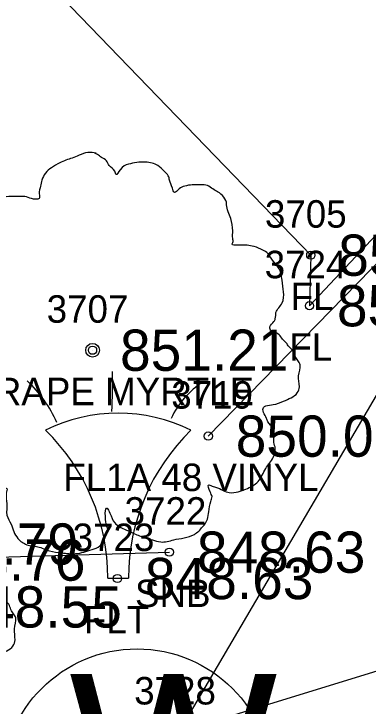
# Model space of a CAD drawing. Extents: x 1622501 to 1626664, y 1117816 to 1121579.
# Drawn here: x 1624875.03 to 1624887.93, y 1120136.59 to 1120161.78 of the extents above; entities that cross this region are included whole.
import ezdxf

# ---------------------------------------------------------------- set-up
doc = ezdxf.new("R2010")
doc.units = 0
for name, color, linetype in [('RD_EX_BldgApp', 7, 'Continuous'), ('RD_EX_BldgApp_txCode', 7, 'Continuous'), ('RD_EX_Fence_Other', 7, 'Continuous'), ('RD_EX_Fence_Other_txCode', 7, 'Continuous'), ('RD_EX_TX_BldgApp_ELEV', 7, 'Continuous'), ('RD_EX_TX_Fence_Other_ELEV', 7, 'Continuous'), ('RD_EX_TX_VEG_ELEV', 7, 'Continuous'), ('RD_EX_UT', 7, 'Continuous'), ('RD_EX_VEG', 7, 'Continuous'), ('RD_EX_VEG_txCode', 7, 'Continuous'), ('RD_SMD_Locator', 7, 'Continuous')]:
    doc.layers.add(name, color=color, linetype=linetype)

msp = doc.modelspace()

# ---------------------------------------------------------------- linework, layer by layer
at = {"layer": 'RD_EX_BldgApp'}
for p, q in [((1624870.501, 1120141.902), (1624880.693, 1120142.191)), ((1624878.454, 1120141.249), (1624879.204, 1120141.249))]:
    msp.add_line(p, q, dxfattribs=at)
for centre, radius, start, end in [((1624840.747, 1120148.587), 37.876, 358.0671, 0.2715), ((1624872.136, 1120144.891), 4.895, 24.3279, 46.2665), ((1624883.717, 1120145.642), 3.283, 123.2906, 154.4886), ((1624878.829, 1120141.249), 5.997, 63.7794, 116.2206), ((1624870.954, 1120141.249), 7.5, 0, 45.8366), ((1624886.704, 1120141.249), 7.5, 134.1634, 180)]:
    msp.add_arc(centre, radius, start, end, dxfattribs=at)
at = {"layer": 'RD_EX_Fence_Other'}
for points in [[(1624882.108, 1120146.413), (1624922.827, 1120188.172), (1624952.576, 1120216.9), (1624993.862, 1120256.562), (1625030.931, 1120289.642), (1625069.578, 1120325.996), (1625106.791, 1120358.455), (1625145.388, 1120394.48), (1625163.872, 1120411.002), (1625180.046, 1120426.703), (1625211.372, 1120456.62), (1625250.442, 1120494.547), (1625284.568, 1120527.631), (1625318.686, 1120557.977), (1625317.764, 1120559.821), (1625354.436, 1120595.487), (1625389.434, 1120629.691)], [(1624858.614, 1120181.158), (1624885.841, 1120152.998), (1624885.793, 1120151.157), (1624925.786, 1120193.73), (1624921.287, 1120199.2), (1624921.287, 1120199.2), (1624965.414, 1120242.441), (1624960.474, 1120248.561)]]:
    msp.add_lwpolyline(points, dxfattribs=at)
at = {"layer": 'RD_EX_UT'}
msp.add_circle((1624879.514, 1120133.762), 4.908, dxfattribs=at)
at = {"layer": 'RD_EX_VEG'}
msp.add_lwpolyline([(1624889.699, 1120150.412), (1624881.041, 1120135.648), (1624900.095, 1120141.509), (1624901.078, 1120146.7)], dxfattribs=at)
for centre, radius in [((1624877.895, 1120149.539), 0.25), ((1624877.883, 1120149.52), 0.0001)]:
    msp.add_circle(centre, radius, dxfattribs=at)
for points in [[(1624878.027, 1120156.706), (1624877.727, 1120156.731), (1624877.403, 1120156.631), (1624877.153, 1120156.531), (1624876.928, 1120156.456), (1624876.703, 1120156.356), (1624876.403, 1120156.181), (1624876.178, 1120155.981), (1624876.053, 1120155.731), (1624876.003, 1120155.507), (1624875.953, 1120155.232), (1624875.953, 1120155.057), (1624875.828, 1120155.032), (1624875.678, 1120155.057), (1624875.428, 1120155.132), (1624875.179, 1120155.132), (1624874.929, 1120155.132), (1624874.579, 1120155.107), (1624874.229, 1120155.107), (1624873.954, 1120155.057), (1624873.629, 1120155.007), (1624873.254, 1120154.882), (1624872.905, 1120154.757), (1624872.605, 1120154.507), (1624872.355, 1120154.032), (1624872.23, 1120153.682), (1624872.08, 1120153.432), (1624872.23, 1120152.983), (1624872.405, 1120152.633), (1624872.43, 1120152.433), (1624872.505, 1120152.008), (1624872.605, 1120151.783), (1624872.73, 1120151.583), (1624872.655, 1120151.558), (1624872.28, 1120151.508), (1624871.98, 1120151.408), (1624871.555, 1120151.183), (1624871.33, 1120150.959), (1624871.23, 1120150.634), (1624871.205, 1120150.284), (1624871.105, 1120150.084), (1624871.03, 1120149.809), (1624871.005, 1120149.734), (1624870.955, 1120149.409), (1624871.055, 1120148.959), (1624871.08, 1120148.61), (1624871.205, 1120148.385), (1624871.355, 1120148.21), (1624871.53, 1120147.96), (1624871.93, 1120147.735), (1624872.255, 1120147.635), (1624872.455, 1120147.61), (1624872.28, 1120147.11), (1624872.23, 1120146.76), (1624872.105, 1120146.361), (1624872.105, 1120146.286), (1624872.055, 1120145.811), (1624872.205, 1120145.486), (1624872.28, 1120145.111), (1624872.455, 1120144.886), (1624872.73, 1120144.586), (1624873.054, 1120144.361), (1624873.554, 1120144.236), (1624873.954, 1120144.261), (1624874.529, 1120144.436), (1624874.779, 1120144.511), (1624874.754, 1120144.336), (1624874.779, 1120143.962), (1624874.779, 1120143.537), (1624874.929, 1120143.212), (1624875.029, 1120142.937), (1624875.179, 1120142.687), (1624875.503, 1120142.462), (1624875.903, 1120142.387), (1624876.328, 1120142.237), (1624876.778, 1120142.162), (1624877.278, 1120142.137), (1624877.877, 1120142.287), (1624878.152, 1120142.412), (1624878.252, 1120142.587), (1624878.452, 1120142.962), (1624878.402, 1120143.187), (1624878.427, 1120143.787), (1624878.527, 1120143.612), (1624878.702, 1120143.262), (1624879.202, 1120142.962), (1624879.602, 1120142.787), (1624880.076, 1120142.637), (1624880.376, 1120142.562), (1624880.851, 1120142.637), (1624881.226, 1120142.712), (1624881.601, 1120142.837), (1624881.901, 1120143.112), (1624882.076, 1120143.387), (1624882.126, 1120143.662), (1624882.2, 1120144.037), (1624882.25, 1120144.211)], [(1624882.25, 1120144.211), (1624882.176, 1120144.386), (1624882.126, 1120144.636), (1624882.2, 1120144.611), (1624882.375, 1120144.561), (1624882.65, 1120144.436), (1624882.875, 1120144.361), (1624883.2, 1120144.386), (1624883.475, 1120144.486), (1624883.925, 1120144.761), (1624884.2, 1120145.236), (1624884.474, 1120145.636), (1624884.549, 1120145.961), (1624884.499, 1120146.186), (1624884.474, 1120146.685), (1624884.275, 1120146.935), (1624884.225, 1120147.06), (1624884.125, 1120147.46), (1624884.2, 1120147.51), (1624884.474, 1120147.56), (1624884.849, 1120147.685), (1624885.124, 1120147.81), (1624885.349, 1120147.985), (1624885.424, 1120148.21), (1624885.399, 1120148.61), (1624885.449, 1120149.009), (1624885.374, 1120149.159), (1624885.274, 1120149.309), (1624885.199, 1120149.509), (1624885.049, 1120149.659), (1624884.949, 1120149.809), (1624884.849, 1120149.909), (1624884.724, 1120150.059), (1624884.549, 1120150.184), (1624884.4, 1120150.234), (1624884.35, 1120150.384), (1624884.499, 1120150.584), (1624884.549, 1120150.684), (1624884.574, 1120150.909), (1624884.799, 1120151.258), (1624884.849, 1120151.658), (1624884.799, 1120152.083), (1624884.749, 1120152.358), (1624884.599, 1120152.633), (1624884.4, 1120152.883), (1624884.275, 1120153.058), (1624884.1, 1120153.183), (1624883.775, 1120153.308), (1624883.525, 1120153.357), (1624883.175, 1120153.357), (1624882.975, 1120153.407), (1624883, 1120153.457), (1624883, 1120153.607), (1624883, 1120153.882), (1624882.925, 1120154.332), (1624882.775, 1120154.832), (1624882.775, 1120154.857), (1624882.675, 1120155.107), (1624882.45, 1120155.307), (1624882.275, 1120155.407), (1624882.076, 1120155.532), (1624881.826, 1120155.557), (1624881.526, 1120155.557), (1624881.251, 1120155.507), (1624881.051, 1120155.407), (1624880.876, 1120155.282), (1624880.801, 1120155.432), (1624880.701, 1120155.731), (1624880.651, 1120155.881), (1624880.501, 1120156.056), (1624880.276, 1120156.256), (1624879.826, 1120156.381), (1624879.202, 1120156.306), (1624878.902, 1120156.106), (1624878.752, 1120155.931), (1624878.702, 1120156.056), (1624878.502, 1120156.256), (1624878.402, 1120156.431), (1624878.227, 1120156.556), (1624878.077, 1120156.656), (1624877.977, 1120156.706)], [(1624871.9, 1120135.002), (1624871.825, 1120135.177), (1624871.775, 1120135.426), (1624871.85, 1120135.401), (1624872.025, 1120135.351), (1624872.3, 1120135.226), (1624872.524, 1120135.152), (1624872.849, 1120135.177), (1624873.124, 1120135.276), (1624873.574, 1120135.551), (1624873.849, 1120136.026), (1624874.124, 1120136.426), (1624874.199, 1120136.751), (1624874.149, 1120136.976), (1624874.124, 1120137.475), (1624873.924, 1120137.725), (1624873.874, 1120137.85), (1624873.774, 1120138.25), (1624873.849, 1120138.3), (1624874.124, 1120138.35), (1624874.499, 1120138.475), (1624874.773, 1120138.6), (1624874.998, 1120138.775), (1624875.073, 1120139), (1624875.048, 1120139.4), (1624875.098, 1120139.799), (1624875.023, 1120139.949), (1624874.923, 1120140.099), (1624874.848, 1120140.299), (1624874.698, 1120140.449), (1624874.599, 1120140.599), (1624874.499, 1120140.699), (1624874.374, 1120140.849), (1624874.199, 1120140.974), (1624874.049, 1120141.024), (1624873.999, 1120141.174), (1624874.149, 1120141.374), (1624874.199, 1120141.474), (1624874.224, 1120141.699), (1624874.449, 1120142.048), (1624874.499, 1120142.448), (1624874.449, 1120142.873), (1624874.399, 1120143.148), (1624874.249, 1120143.423), (1624874.049, 1120143.673), (1624873.924, 1120143.848), (1624873.749, 1120143.973), (1624873.424, 1120144.098), (1624873.174, 1120144.148), (1624872.824, 1120144.148), (1624872.624, 1120144.198), (1624872.649, 1120144.248), (1624872.649, 1120144.397), (1624872.649, 1120144.672), (1624872.574, 1120145.122), (1624872.424, 1120145.622), (1624872.424, 1120145.647), (1624872.324, 1120145.897), (1624872.1, 1120146.097), (1624871.925, 1120146.197), (1624871.725, 1120146.322), (1624871.475, 1120146.347), (1624871.175, 1120146.347), (1624870.9, 1120146.297), (1624870.7, 1120146.197), (1624870.525, 1120146.072), (1624870.45, 1120146.222), (1624870.35, 1120146.522), (1624870.3, 1120146.671), (1624870.15, 1120146.846), (1624869.926, 1120147.046), (1624869.476, 1120147.171), (1624868.851, 1120147.096), (1624868.551, 1120146.896), (1624868.401, 1120146.721), (1624868.351, 1120146.846), (1624868.151, 1120147.046), (1624868.051, 1120147.221), (1624867.876, 1120147.346), (1624867.727, 1120147.446), (1624867.627, 1120147.496)]]:
    msp.add_spline(points, degree=3, dxfattribs=at)
at = {"layer": 'RD_SMD_Locator'}
for centre in [(1624885.841, 1120152.998), (1624885.793, 1120151.157), (1624877.895, 1120149.539), (1624882.108, 1120146.413), (1624880.693, 1120142.191), (1624878.801, 1120141.231)]:
    msp.add_circle(centre, 0.15, dxfattribs=at)

# ---------------------------------------------------------------- texts
at = {"layer": 'RD_EX_BldgApp_txCode'}
for s, p in [('3722', (1624879.063, 1120143.191)), ('3723', (1624877.171, 1120142.231)), ('SNB', (1624879.441, 1120140.191)), ('FLT', (1624877.581, 1120139.231))]:
    msp.add_text(s, height=1, dxfattribs=at).set_placement(p)
at = {"layer": 'RD_EX_Fence_Other_txCode'}
for s, p in [('3705', (1624884.171, 1120153.998)), ('3724', (1624884.163, 1120152.157)), ('FL', (1624885.108, 1120150.998)), ('FL', (1624885.061, 1120149.157)), ('3719', (1624880.762, 1120147.413)), ('FL1A 48 VINYL', (1624876.833, 1120144.413))]:
    msp.add_text(s, height=1, dxfattribs=at).set_placement(p)
at = {"layer": 'RD_EX_TX_BldgApp_ELEV'}
for s, p in [('848.63', (1624881.693, 1120141.441)), ('848.76', (1624871.501, 1120141.152)), ('848.63', (1624879.801, 1120140.481)), ('848.55', (1624872.829, 1120139.448))]:
    msp.add_text(s, height=1.5, dxfattribs=at).set_placement(p)
at = {"layer": 'RD_EX_TX_Fence_Other_ELEV'}
for s, p in [('851.98', (1624886.841, 1120152.248)), ('851.52', (1624886.793, 1120150.407)), ('850.02', (1624883.108, 1120145.663)), ('848.79', (1624871.233, 1120141.736))]:
    msp.add_text(s, height=1.5, dxfattribs=at).set_placement(p)
at = {"layer": 'RD_EX_TX_VEG_ELEV'}
msp.add_text('851.21', height=1.5, dxfattribs=at).set_placement((1624878.895, 1120148.789))
at = {"layer": 'RD_EX_UT'}
msp.add_text('W', height=6, dxfattribs=at).set_placement((1624877.05, 1120131.761))
at = {"layer": 'RD_EX_VEG_txCode'}
for s, p in [('3707', (1624876.226, 1120150.539)), ('T 15 CRAPE MYRTLE', (1624870.325, 1120147.539)), ('3728', (1624879.411, 1120136.648))]:
    msp.add_text(s, height=1, dxfattribs=at).set_placement(p)

doc.saveas('drawing.dxf')
